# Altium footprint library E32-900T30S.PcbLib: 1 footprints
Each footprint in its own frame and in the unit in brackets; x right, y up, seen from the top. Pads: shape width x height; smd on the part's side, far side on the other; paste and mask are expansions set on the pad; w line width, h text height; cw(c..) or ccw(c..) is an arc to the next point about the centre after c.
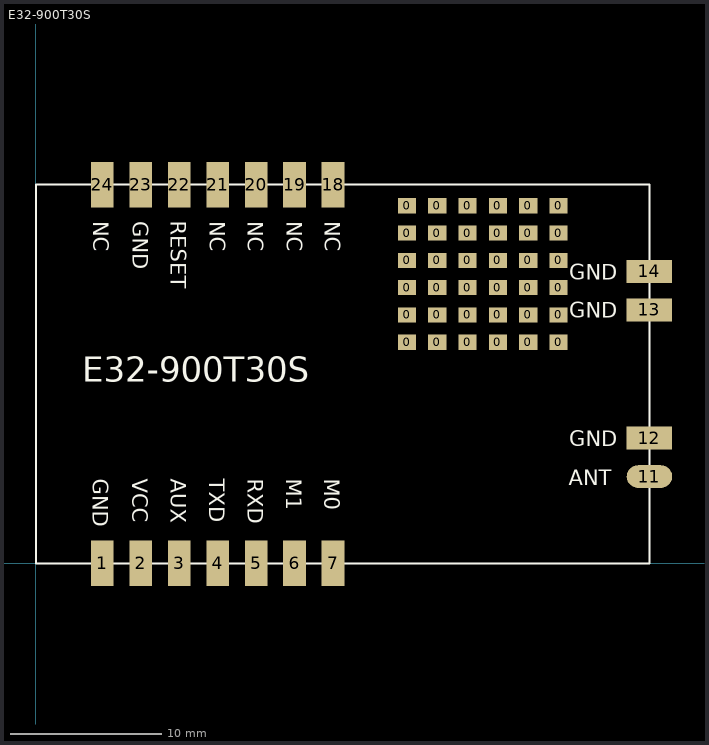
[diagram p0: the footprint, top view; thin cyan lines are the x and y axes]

## E32-900T30S [mm]
pads (54):
  rect 1.2x1 smd: 0(24.5,14.6) 0(24.5,16.4) 0(24.5,18.2) 0(24.5,20) 0(24.5,21.8) 0(24.5,23.6) 0(26.5,14.6) 0(26.5,16.4) 0(26.5,18.2) 0(26.5,20) 0(26.5,21.8) 0(26.5,23.6) 0(28.5,14.6) 0(28.5,16.4) 0(28.5,18.2) 0(28.5,20) 0(28.5,21.8) 0(28.5,23.6) 0(30.5,14.6) 0(30.5,16.4) 0(30.5,18.2) 0(30.5,20) 0(30.5,21.8) 0(30.5,23.6) 0(32.5,14.6) 0(32.5,16.4) 0(32.5,18.2) 0(32.5,20) 0(32.5,21.8) 0(32.5,23.6) 0(34.5,14.6) 0(34.5,16.4) 0(34.5,18.2) 0(34.5,20) 0(34.5,21.8) 0(34.5,23.6)
  rect 1.5x3 smd: 1(4.38,0) 2(6.92,0) 3(9.46,0) 4(12,0) 5(14.54,0) 6(17.08,0) 7(19.62,0) 18(19.62,25) 19(17.08,25) 20(14.54,25) 21(12,25) 22(9.46,25) 23(6.92,25) 24(4.38,25)
  oval 3x1.5 smd: 11(40.5,5.73)
  rect 3x1.5 smd: 12(40.5,8.27) 13(40.5,16.73) 14(40.5,19.27)
Top Overlay:
  lines w0.127: 0,0 40.5,0 40.5,25 0,25 0,0
  text "RESET" at 8.89,22.606 h1
  text "GND" at 35.222,18.73 h1
  text "GND" at 35.222,16.22 h1
  text "NC" at 19.063,22.592 h1
  text "NC" at 16.553,22.592 h1
  text "NC" at 14.003,22.592 h1
  text "NC" at 11.473,22.592 h1
  text "GND" at 6.383,22.592 h1
  text "NC" at 3.793,22.592 h1
  text "GND" at 3.773,5.575 h1
  text "VCC" at 6.363,5.575 h1
  text "AUX" at 8.913,5.575 h1
  text "TXD" at 11.453,5.575 h1
  text "RXD" at 13.983,5.575 h1
  text "M1" at 16.533,5.575 h1
  text "M0" at 19.043,5.575 h1
  text "ANT" at 35.174,5.17 h1
  text "GND" at 35.222,7.72 h1
  text "E32-900T30S" at 3.048,11.43 h2.8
